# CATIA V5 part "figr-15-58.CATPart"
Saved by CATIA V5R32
Part number: Part1
Bounding box of the stored display mesh (mm): x -20 to 20, y -25 to 25, z 0 to 50
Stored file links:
  D:\PROJECTS\Project 2022\CATIA V5 6R 2022\Resources\Part Files\c15_catia_v5_6r2022_prt\figr-15-58.CATPart
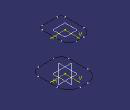
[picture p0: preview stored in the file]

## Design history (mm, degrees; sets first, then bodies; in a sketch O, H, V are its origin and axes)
SheetMetalParameters1: Thickness 2, BendRadius 4, KFactor 0.400515 {= log(min(100,max(20*SheetMetalParameters1.BendRadius,SheetMetalParameters1.Thickness)/SheetMetalParameters1.Thickness))/log(100)/2}, ReliefRadialLength 1, ReliefAxialLength 2, MinimumBendRadius 0
Body1 (main body)
  Plane1: type Offset, RefPlane xy-plane, Offset 50
  Sketch1 on xy-plane, origin (0, 0, 0), H (1, 0, 0), V (0, 1, 0)
    line L1 (20, 10) -> (20, -15)
    line L2 (10, -25) -> (-10, -25)
    line L3 (-20, -15) -> (-20, 10)
    line L4 (-5, 25) -> (5, 25)
    arc A1 centre (5, 10) radius 15 from (20, 10) to (5, 25) ccw
    arc A2 centre (-5, 10) radius 15 from (-20, 10) to (-5, 25) cw
    arc A3 centre (10, -15) radius 10 from (20, -15) to (10, -25) cw
    arc A4 centre (-10, -15) radius 10 from (-10, -25) to (-20, -15) cw
    radius A1 = 15
    radius A2 = 15
    radius A3 = 10
    radius A4 = 10
    distance L4 L2 = 50
    distance L3 L1 = 40
    vertical: L1 V, L3 V
    horizontal: L2 H, L4 H
    equidistance: L1 L3 O, L2 L4 O
    tangency: A1 L1, A1 L4, A2 L3, A2 L4, A3 L1, A3 L2, A4 L2, A4 L3
  Sketch2 on Plane1, origin (0, 0, 50), H (1, 0, 0), V (0, 1, 0)
    line L1 (15, 10) -> (15, -15)
    line L2 (10, -20) -> (-10, -20)
    line L3 (-15, -15) -> (-15, 10)
    line L4 (-5, 20) -> (5, 20)
    arc A1 centre (5, 10) radius 10 from (15, 10) to (5, 20) ccw
    arc A2 centre (10, -15) radius 5 from (15, -15) to (10, -20) cw
    arc A3 centre (-10, -15) radius 5 from (-10, -20) to (-15, -15) cw
    arc A4 centre (-5, 10) radius 10 from (-15, 10) to (-5, 20) cw
    radius A1 = 10
    radius A2 = 5
    radius A3 = 5
    radius A4 = 10
    distance L4 L2 = 40
    distance L1 L3 = 30
    vertical: L1 V, L3 V
    horizontal: L2 H, L4 H
    equidistance: L1 L3 O, L2 L4 O
    tangency: A1 L1, A1 L4, A2 L1, A2 L2, A3 L2, A3 L3, A4 L3, A4 L4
